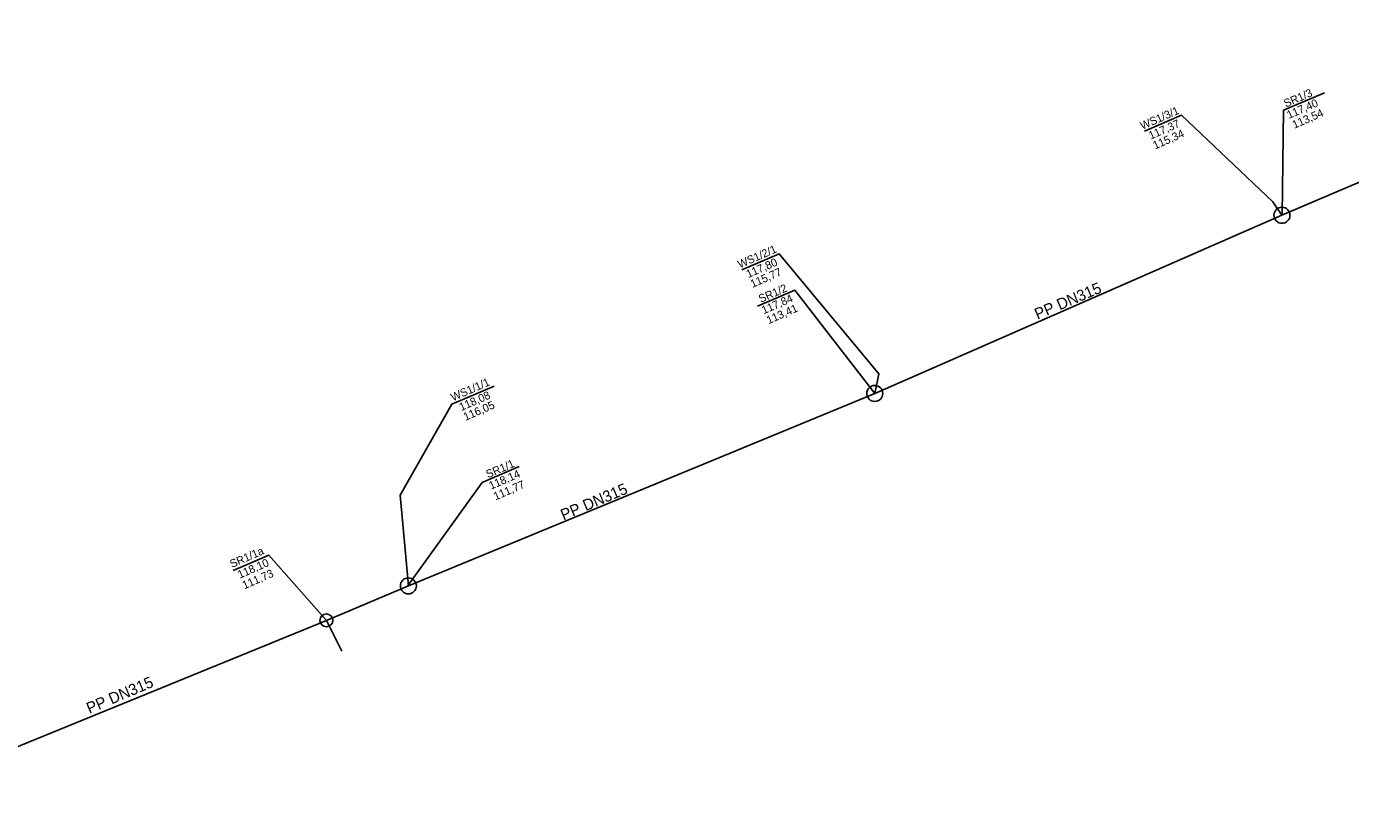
# Model space of a CAD drawing. Extents: x 7499288 to 7500494, y 5768505 to 5769051.
# Drawn here: x 7499889.5 to 7500013.6, y 5768767.6 to 5768838.9 of the extents above; entities that cross this region are included whole.
import ezdxf

# ---------------------------------------------------------------- set-up
doc = ezdxf.new("R2010")
doc.units = 0
for name, color, linetype in [('1_proj_kd_etap1', 7, 'Continuous'), ('1_proj_kd_etap2', 7, 'Continuous'), ('2_opisy_KD_etap1', 7, 'Continuous')]:
    doc.layers.add(name, color=color, linetype=linetype)

msp = doc.modelspace()

# ---------------------------------------------------------------- linework, layer by layer
at = {"layer": '1_proj_kd_etap1'}
for p, q in [((7500007.15, 5768821.26), (7500048.35, 5768838.95)), ((7500007.15, 5768821.26), (7500006.28, 5768822.51)), ((7500007.15, 5768821.26), (7499968.98, 5768804.57)), ((7499969.36, 5768806.42), (7499968.98, 5768804.57)), ((7499925.27, 5768786.54), (7499968.98, 5768804.57)), ((7499925.28, 5768786.55), (7499924.49, 5768795.05)), ((7499917.59, 5768783.31), (7499925.27, 5768786.54)), ((7499919.03, 5768780.42), (7499917.59, 5768783.31))]:
    msp.add_line(p, q, dxfattribs=at)
for centre, radius in [((7500007.15, 5768821.26), 0.75), ((7499968.98, 5768804.57), 0.75), ((7499925.27, 5768786.54), 0.75), ((7499917.59, 5768783.31), 0.605)]:
    msp.add_circle(centre, radius, dxfattribs=at)
at = {"layer": '1_proj_kd_etap2'}
msp.add_line((7499917.59, 5768783.31), (7499879.26, 5768767.65), dxfattribs=at)
at = {"layer": '2_opisy_KD_etap1'}
for points in [[(7500011.13, 5768832.74), (7500007.3, 5768831.1), (7500007.18, 5768821.27)], [(7499994.26, 5768829.13), (7499997.74, 5768830.63), (7500006.28, 5768822.51)], [(7499956.53, 5768816.15), (7499960.02, 5768817.65), (7499969.36, 5768806.41)], [(7499957.99, 5768812.76), (7499961.48, 5768814.26), (7499968.98, 5768804.57)], [(7499933.3, 5768805.26), (7499929.34, 5768803.56), (7499924.49, 5768795.05)], [(7499935.66, 5768797.71), (7499932.2, 5768796.22), (7499925.18, 5768786.5)], [(7499908.84, 5768787.97), (7499912.21, 5768789.42), (7499917.59, 5768783.31)]]:
    msp.add_lwpolyline(points, dxfattribs=at)

# ---------------------------------------------------------------- texts
for s, height, rotation, p in [('SR1/3', 0.75, 23.5988, (7500007.52, 5768831.35)), ('117,40', 0.75, 23.5988, (7500007.8, 5768830.28)), ('WS1/3/1', 0.75, 23.5988, (7499994.06, 5768829.26)), ('113,54', 0.75, 23.5988, (7500008.31, 5768829.36)), ('117,37', 0.75, 23.5988, (7499994.85, 5768828.35)), ('115,34', 0.75, 23.5988, (7499995.25, 5768827.42)), ('WS1/2/1', 0.75, 23.5988, (7499956.34, 5768816.28)), ('117,80', 0.75, 23.5988, (7499957.13, 5768815.37)), ('115,77', 0.75, 23.5988, (7499957.52, 5768814.45)), ('SR1/2', 0.75, 23.5988, (7499958.3, 5768813.05)), ('PP DN315', 1.05, 22.9552, (7499984.23, 5768811.47)), ('117,84', 0.75, 23.5988, (7499958.58, 5768811.98)), ('113,41', 0.75, 23.5988, (7499959.03, 5768811.05)), ('WS1/1/1', 0.75, 23.5988, (7499929.45, 5768803.82)), ('118,08', 0.75, 23.5988, (7499930.23, 5768802.91)), ('116,05', 0.75, 23.5988, (7499930.63, 5768801.99)), ('SR1/1', 0.75, 23.5988, (7499932.74, 5768796.61)), ('118,14', 0.75, 23.5988, (7499933.02, 5768795.54)), ('111,77', 0.75, 23.5988, (7499933.45, 5768794.54)), ('PP DN315', 1.05, 22.9552, (7499939.81, 5768792.65)), ('SR1/1a', 0.75, 23.5988, (7499908.74, 5768788.21)), ('118,10', 0.75, 23.5988, (7499909.47, 5768787.21)), ('111,73', 0.75, 23.5988, (7499909.9, 5768786.21)), ('PP DN315', 1.05, 22.9552, (7499895.37, 5768774.54))]:
    msp.add_text(s, height=height, rotation=rotation, dxfattribs=at).set_placement(p)

doc.saveas('drawing.dxf')
